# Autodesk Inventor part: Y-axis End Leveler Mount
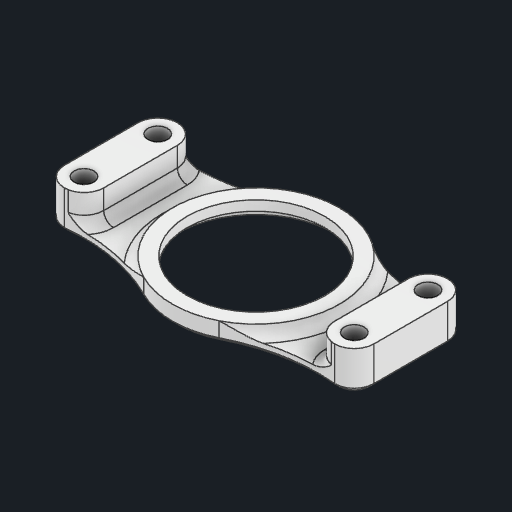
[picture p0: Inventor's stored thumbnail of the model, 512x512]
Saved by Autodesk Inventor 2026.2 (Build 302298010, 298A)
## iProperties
Created: 2026-04
Part Number: Y-axis End Leveler Mount
Material: PBT 플라스틱
Document SubType Name: Modeling
Designer: work
Density: 1.31 g/cm^3
Appearance: 매끄러움 - 흰색
Author: work
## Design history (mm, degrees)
sketch "스케치1"
  geometry: L1 (27.5, 7.5)-(27.5, -7.5); L2 (27.5, 0)-(0, 0); L3 (0, 17)-(0, -17); L4 (27.5, 7.5)-(27.5, -7.5); L5 (23.5, 7.5)-(23.5, -7.5); L6 (31.5, -7.5)-(31.5, 7.5); L7 (-27.5, 0)-(0, 0); L8 (-31.5, -7.5)-(-31.5, 7.5); L9 (-27.5, 7.5)-(-27.5, -7.5); L10 (-27.5, 7.5)-(-27.5, -7.5); L11 (-23.5, 7.5)-(-23.5, -7.5); C1 r 2 at (27.5, 7.5); C2 r 2 at (27.5, -7.5); C3 r 2 at (-27.5, -7.5); C4 r 2 at (-27.5, 7.5); C5 r 16 at (0, 0); C6 r 14 at (0, 0); A1 r 17 centre (0, 0) between (0, 17) and (0, -17); A2 r 4 centre (27.5, 7.5) between (31.5, 7.5) and (23.5, 7.5); A3 r 4 centre (27.5, -7.5) between (23.5, -7.5) and (31.5, -7.5); A4 r 36 centre (23.876, 47.317) between (7.658, 15.177) and (27.5, 11.5); A5 r 36 centre (23.876, -47.317) between (27.5, -11.5) and (7.658, -15.177); A6 r 4 centre (-27.5, -7.5) between (-31.5, -7.5) and (-23.5, -7.5); A7 r 36 centre (-23.876, -47.317) between (-7.658, -15.177) and (-27.5, -11.5); A8 r 4 centre (-27.5, 7.5) between (-23.5, 7.5) and (-31.5, 7.5); A9 r 36 centre (-23.876, 47.317) between (-27.5, 11.5) and (-7.658, 15.177); 12 further points
  constraints: 26 end point, 20 point on circle, 19 symmetric about line, 15 centre point, 7 coincident, 5 tangent, 3 vertical, 2 midpoint, 1 horizontal, 1 parallel, 7 other
  dimensions: "d0" = 34 diameter of A1; "d1" = 4 diameter of C1; "d2" = 4 diameter of C2; "d3" = 15 distance of L1.start L1.end; "d4" = 28.504 distance of L4.end L2.end; "d5" = 34 distance of L3.start L3.end; "d6" = 4 radius of A3; "d7" = 36 radius of A4; "d8" = 32 diameter of C5; "d9" = 2 radial gap between concentric circles of C6 C5
extrude "돌출1" new body sketch "스케치1" distance "d10" = 2; taper "d11" = 0 deg
extrude "돌출2" join sketch "스케치1" distance "d12" = 8; taper "d13" = 0 deg
extrude "돌출3" join sketch "스케치1" distance "d14" = 2; taper "d15" = 0 deg
sketch "스케치2"
  geometry: L1 (23.5, -7.5)-(23.5, 7.5) reference; L2 (-23.5, 7.5)-(-23.5, -7.5) reference; C1 r 16 at (0, 0) reference; C2 r 14 at (0, 0); C3 r 17 at (0, 0); A1 r 4 centre (-27.5, -7.5) between (-26.778, -11.434) and (-23.5, -7.5) reference; A2 r 36 centre (-23.876, -47.317) between (-7.658, -15.177) and (-26.778, -11.434) reference; A3 r 17 centre (0, 0) between (-7.658, -15.177) and (7.658, -15.177) reference; A4 r 36 centre (23.876, -47.317) between (26.778, -11.434) and (7.658, -15.177) reference; A5 r 4 centre (27.5, -7.5) between (23.5, -7.5) and (26.778, -11.434) reference; A6 r 4 centre (27.5, 7.5) between (26.778, 11.434) and (23.5, 7.5) reference; A7 r 36 centre (23.876, 47.317) between (7.658, 15.177) and (26.778, 11.434) reference; A8 r 17 centre (0, 0) between (7.658, 15.177) and (-7.658, 15.177) reference; A9 r 36 centre (-23.876, 47.317) between (-26.778, 11.434) and (-7.658, 15.177) reference; A10 r 4 centre (-27.5, 7.5) between (-23.5, 7.5) and (-26.778, 11.434) reference; 5 further points
  constraints: 2 centre point, 2 coincident, 1 tangent
  dimensions: "d16" = 2 radial gap between concentric circles of C1 C2
extrude "돌출4" join sketch "스케치2" distance "d17" = 2; taper "d18" = 0 deg
fillet "모깎기1" dims "d19" = 2
chamfer "모따기1" distance "d20" = 1; stored, may be unused: second distance "d21" = 2, angle "d22" = 45 deg
feature "Ǚ耀Ǜ耀ǝ耀ǟ耀ǡ耀ǣ耀ǥ耀ǧ耀" dims "d0" = 34, "d1" = 4, "d2" = 4, "d3" = 15, "d4" = 28.504, "d5" = 34, "d6" = 4, "d7" = 36, "d8" = 32, "d9" = 2, "d10" = 2, "d11" = 0, "d12" = 8, "d13" = 0, "d14" = 2, "d15" = 0, "d16" = 2, "d17" = 2, "d18" = 0, "d19" = 2, "d20" = 1, "d21" = 2, "d22" = 45 deg
node "솔리드1"
node "투영된 루프1"
